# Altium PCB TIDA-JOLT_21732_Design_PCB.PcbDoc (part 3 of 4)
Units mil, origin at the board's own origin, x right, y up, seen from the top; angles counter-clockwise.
Board outline 5511.81 x 3149.61 mil, 4 copper layers (Top Layer, Power, Ground, Bottom Layer), stack 104.204 mil thick; 440 components, 201 nets, 1044 pads, 391 vias.
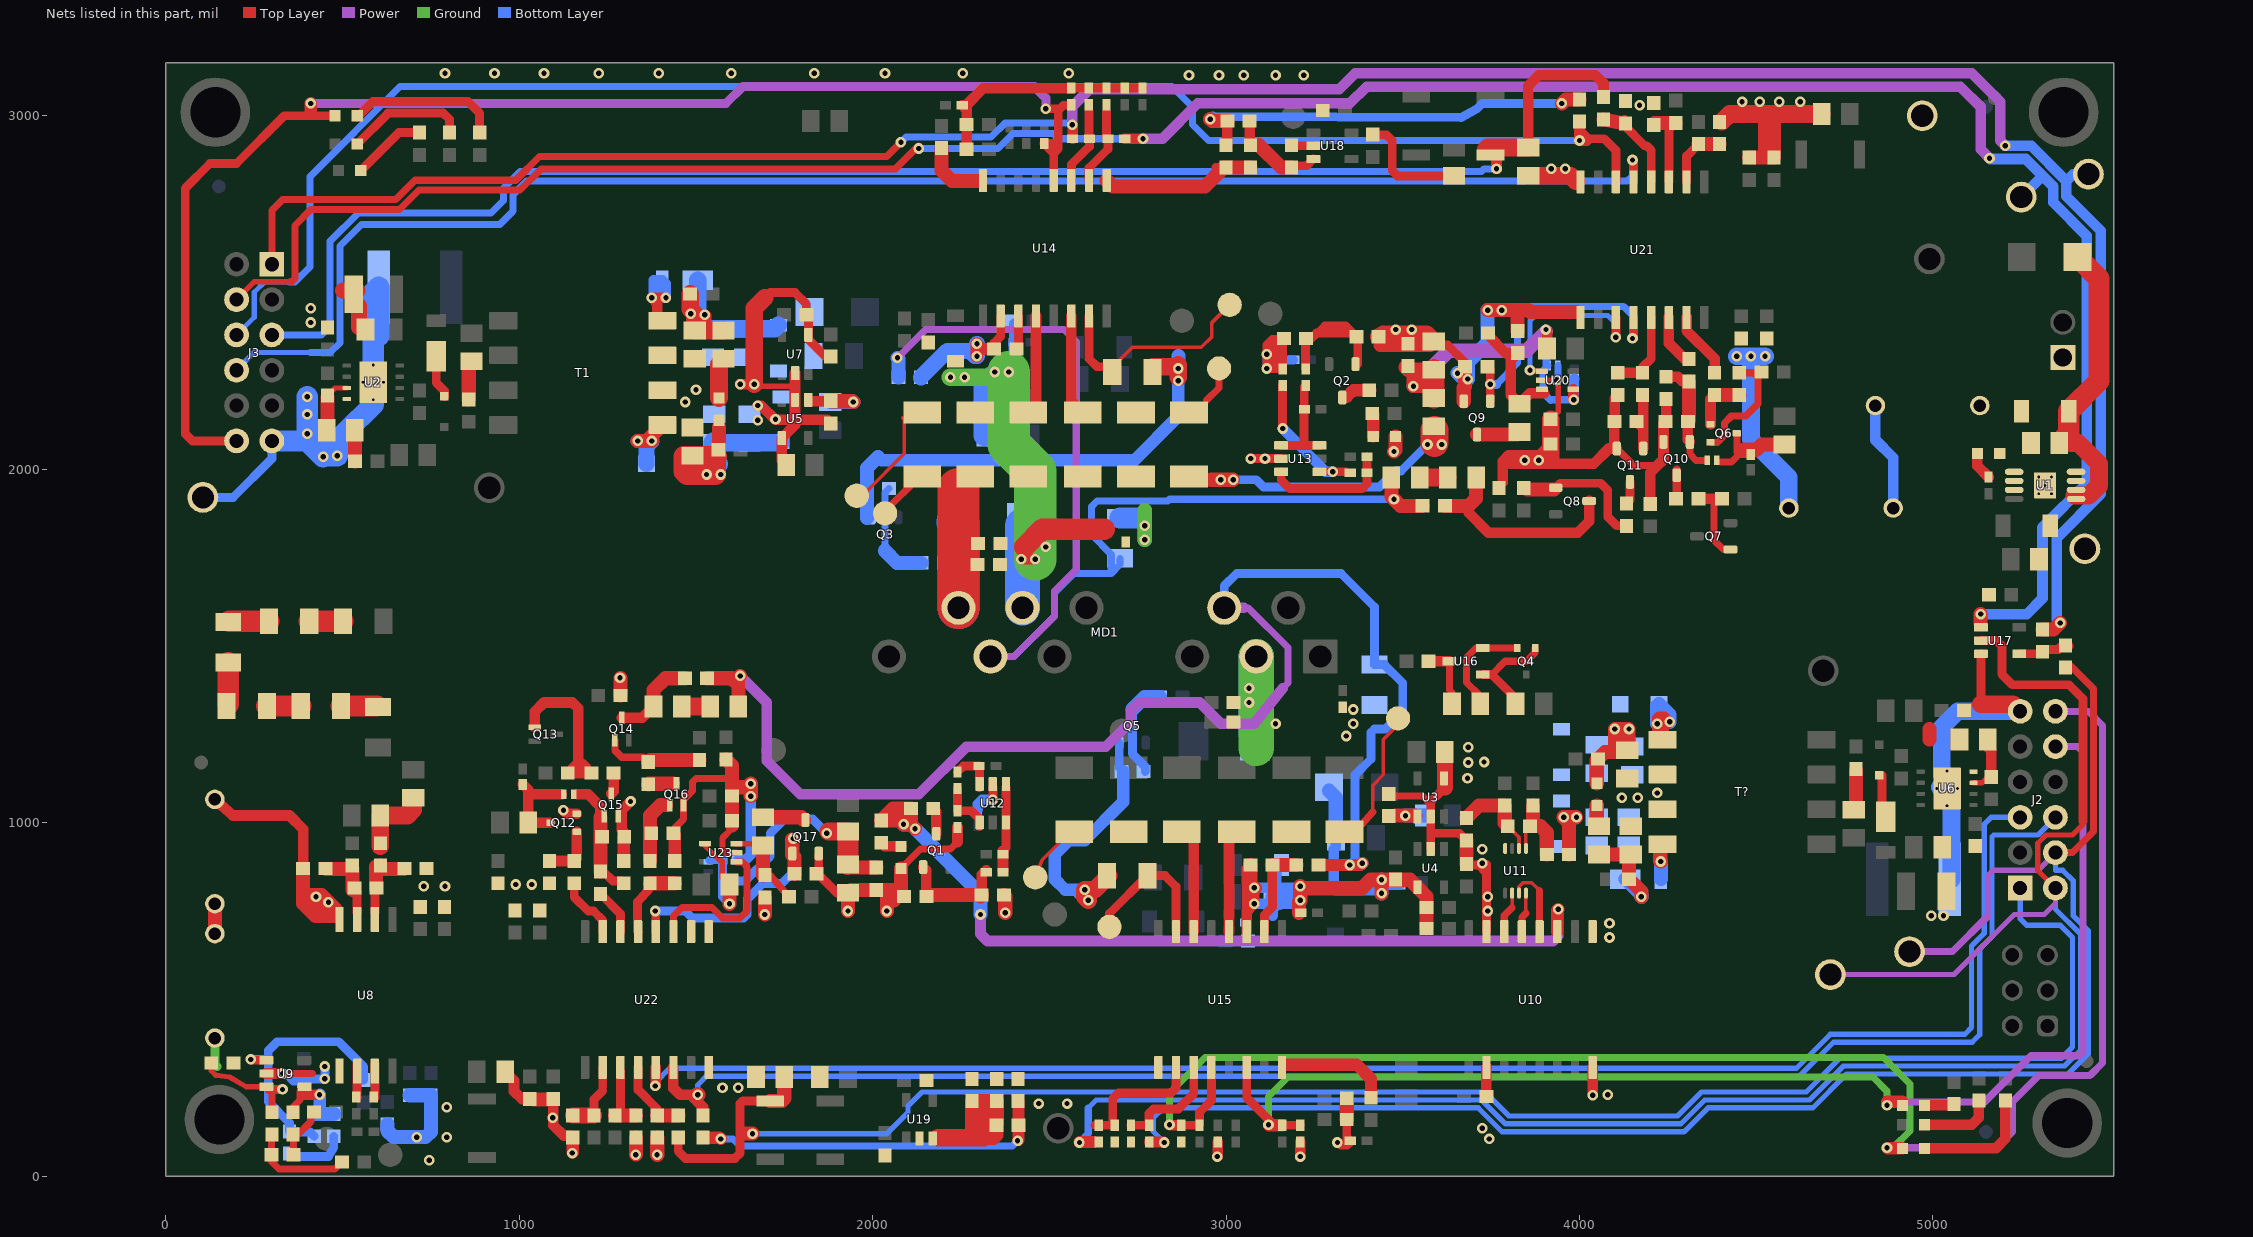
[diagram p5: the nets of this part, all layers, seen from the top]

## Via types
v1: diameter 30, hole 15, Top Layer to Bottom Layer, 378 vias
v2: diameter 19.68, hole 7.87, Top Layer to Bottom Layer, 13 vias

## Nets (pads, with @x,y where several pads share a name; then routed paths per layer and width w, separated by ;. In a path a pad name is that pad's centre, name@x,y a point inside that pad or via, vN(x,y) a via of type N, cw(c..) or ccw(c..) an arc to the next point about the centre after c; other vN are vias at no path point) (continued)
Gate_U: C80.1 D21.2 MD1.13 R63.2 R65.2 R66.2 R67.2 R68.2 R69.2 R70.2 R79.2 R122.2 TP11.1 | length 1515.2
  Top Layer w20: TP11.1@2035,1875 2035,1881.34 2133.11,1979.45 R70.2@2140,1979.45
  Top Layer w40: R63.2@2595,1979.45 R63.2@2598.5,1975.94 ; 2957.99,1970 v1(2985,1970) v1(3020,1970)
  Top Layer w80: 3590,2075 R122.2@3590,2110
  Top Layer w120: MD1.13@2242.76,1607.8 2242.76,1942.76
  Bottom Layer w25: v1(2985,1970) v1(3020,1970) 3085,1970 3105,1950 3435,1950 3480,1995 3495,1995 v1(3570,2070) v1(3610,2070)
  Bottom Layer w120: D21.2@2240.17,1850 2242.76,1847.42 MD1.13@2242.76,1607.8
GND: C1.2 C2.2 C3.2 C4.2 C5.2 C10.2 C11.2 C15.2 C17.2 C23.2 C24.2 C25.2 C36.2 C38.2 C43.2 C44.1 C46.1 C49.2 C55.1 C68.1 C71.2 C81.2 C82.2 C83.2 C84.2 C85.2 C86.2 C89.1 C90.2 C92.2 C93.2 C94.2 C95.2 C96.2 C97.2 C100.2 C101.1 C102.1 C103.2 C104.1 C105.2 C106.1 C108.1 C112.2 C118.1 C120.1 C121.1 C125.2 C132.1 C134.1 C135.1 C136.1 D7.1 J1.1 J2.11 J3.11 R9.1 R11.1 R20.1 R21.1 R40.1 R114.1 R115.1 R116.1 R117.1 R118.2 R120.2 R126.2 R143.2 R145.2 R151.2 TP2.1 TP23.1 TP24.1 U1.3 U1.4 U1.5 U1.6 U1.7 U1.9 U2.8 U2.9@587.1,2245.76 U6.8 U6.9@5040.13,1096.84 U8.5 U9.2 U10.2 U10.8 U14.9 U15.9 U17.3 U18.2 U19.2 U21.8 U22.8 | length 6379.4
  Top Layer w20: v1(330,290) 415,290
  Top Layer w25: C83.2@2561.65,3078.35 C85.2@2763.31,3078.35 ; 2971.5,2853.5 C103.2@3068.7,2853.5 ; R115.1@3185,2921.5 3191.5,2915 U18.2@3246.97,2915 ; C90.2@3341.5,160 3341.5,109.88 C97.2@3351.38,100 ; R114.1@3415,2946.5 3453.5,2946.5 3470,2930 3470,2845 3485,2830 R126.2@3645,2830 ; 5135,1335 5135.87,1335.87 U17.3@5135.87,1477.6
  Top Layer w30: U9.2@284.61,290 v1@326.44,290 ; R145.2@960,295 985,270 985,240 1007.99,217.01 C125.2@1041.3,217.01 ; 1096.3,143.7 1126.5,113.5 C136.1@1146.46,113.5 ; v1@1096.3,153.7 C121.1@1096.3,218.5 ; C86.2@2253.62,3030 2265.68,3017.94 ; C68.1@2265.68,2905.35 C71.2@2265.68,2975.35 2265.68,3017.94 ; C83.2@2561.65,3078.35 2313.35,3078.35 2265.68,3030.68 2265.68,3017.94 ; v1@2976.06,56.06 C95.2@2976.06,96.38 ; v1(3210,55) C96.2@3210,96.38 ; v1@3325.79,90 3341.38,90 C97.2@3346.38,95 ; C55.1@3736.5,225 3736.5,306.89 U10.2@3737.05,307.44 ; v1@4037.05,233.43 U10.8@4037.05,307.44
  Top Layer w35: v1@1151.46,66.46 C136.1@1151.46,108.5
  Top Layer w40: R11.1@535,2110 535.51,2035.17 R9.1@535.6,2022.61 ; C125.2@1041.3,217.01 C121.1@1091.3,217.01 ; v1@1330.58,60.58 C134.1@1330.58,108.5 ; v1@1390.29,60.29 C132.1@1390.29,108.5 ; U14.9@2662.18,2817.28 2679.46,2800 2940,2800 2993.5,2853.5 C104.1@3000,2853.5 C103.2@3068.7,2853.5 ; C90.2@3341.5,160 C89.1@3341.5,220 ; C108.1@4480,2881.5 4525,2881.5 ; 4525,2980 4525,2881.5 ; 4550,3005 C112.2@4550,2881.5 4525,2881.5 ; 4990,1235 4990,1265
  Top Layer w45: 500.76,2505.76 C2.2@542.13,2505.76 ; C3.2@547.1,2401.5 C2.2@547.1,2462.1
  Top Layer w50: R118.2@3855,2830 3975,2830 3990,2815 ; C135.1@4402.8,2982.8 4425,3005 4550,3005 R120.2@4685,3005 ; 5135,1335 5226.73,1335 J2.11@5246.77,1314.96
  Ground w25: C36.2@138.7,390.47 138.7,316.3 145,310
  Bottom Layer w25: TP23.1@105,1920 190,1920 300,2030 J3.11@300,2080 ; v1(330,290) 340,290 361.5,268.5 C44.1@390,268.5 396.5,275 v1(450,275) v1(450,310)
  Bottom Layer w30: v1(330,290) v1@330.47,289.53
  Bottom Layer w40: C49.2@626.69,146.54 626.69,128.31 645,110 v1(710,110) 735,110 750,125 C43.2@750,223.5 ; C46.1@690,228.5 C43.2@750,228.5
  Bottom Layer w50: v2@5020,1100 5052.36,1067.64 C23.2@5052.36,840 ; 5025,1135 5025,1270 5069.96,1314.96 ; 5077.76,1314.96 5069.96,1314.96 ; J2.11@5246.77,1314.96 5069.96,1314.96
  Bottom Layer w60: J3.11@300,2080 400,2080 ; v1(400,2205) v1(400,2155) v1(400,2100) 400,2080 ; 511.85,2108.15 510,2106.3 ; 602.64,2377.36 C1.2@602.64,2515 587.1,2499.46 v2(587.1,2294.97) v2(587.1,2196.55) 587.1,2183.39 510,2106.3 ; 400,2080 483.7,2080 510,2106.3 ; 400,2080 v1(445,2035) 448.03,2038.03 v1(485,2038.03) 485,2081.3 510,2106.3
  other v1: 745,45 2975,55 1330,60 1390,60 1150,65 3315,95 3745,105 795,110 3725,135 1095,165 795,195 2470,205 2550,205 4037.05,228.43 4080,230 1575,250 1620,250 4995,736.65 5030,736.65 410,2415 410,2455 3920,2850 3960,2850 4170,3030 4460,3040 4510,3040 4565,3040 4625,3040 2895,3115 2980,3115 3050,3115 3140,3115 3220,3115 790,3120 930,3120 1070,3120 1225,3120 1395,3120 1600,3120 1835,3120 2035,3120 2255,3120 2555,3120
  other v2: 5040.13,1047.63 5010.99,1096.84 5069.26,1096.84 5040.13,1146.06 5299.69,1930.51 5335.12,1930.51 5317.4,1954.13 5299.69,1977.76 5335.12,1977.76 557.96,2245.76 616.23,2245.76
INL+: J2.2 R88.2 TP14.1 U17.2 | length 5392.5
  Top Layer w15: J2.2@5346.77,814.96 5296.72,865.01 5296.72,941.72 5320.01,965.01 5395.01,965.01 5424.68,994.68 5424.68,1005
  Top Layer w25: U17.2@5135.87,1515 5180,1515 5195,1500 5195,1420 5225,1390 5385,1390 5424.68,1350.32 5424.68,1005
  Top Layer w35: v1@2586.38,96.38 R88.2@2628.19,96.38
  Power w15: TP14.1@4710,570 5060,570 5230,740 5315.04,740 5346.77,771.73 J2.2@5346.77,814.96
  Bottom Layer w15: 2610,192.8 2632.5,215.3 ; 2635,215.3 2632.5,215.3 ; J2.2@5346.77,814.96 5346.77,754.98 5417.45,684.3 5417.45,355.7 5372.8,311.06 4746.55,311.06 4650.79,215.3 4354.3,215.3 4286.55,147.55 3790.68,147.55 3722.93,215.3 2632.5,215.3
  Bottom Layer w20: v1(2585,95) 2610,120 2610,192.8
INL-: J2.4 R90.2 R109.2 TP16.1 | length 4744.8
  Top Layer w20: J2.4@5346.77,914.96 5394.96,914.96 5454.63,974.63 5454.63,1378.88 R109.2@5390,1443.5
  Top Layer w30: R90.2@2782.13,96.38 v1@2823.62,96.38
  Power w15: 5155,735 5155,850 5170,865 5296.81,865 J2.4@5346.77,914.96
  Power w20: TP16.1@4933.78,635 5055,635 5155,735
  Bottom Layer w15: v1(2825,95) 2793.94,126.06 2793.94,163.94 2822.85,192.85 3713.63,192.85 3781.38,125.1 4295.85,125.1 4363.6,192.85 4660.09,192.85 4755.85,288.61 5382.1,288.61 5439.9,346.4 5439.9,693.6 5396.72,736.78 5396.72,835.65 5367.46,864.91 5346.77,864.91 J2.4@5346.77,914.96
INU+: J3.4 R62.2 TP13.1 U17.1 | length 7295.8
  Top Layer w15: J3.4@200,2480 250,2530 355,2530
  Top Layer w20: 355,2530 365,2540 365,2690 410.1,2735.1 661.37,2735.1 716.37,2790.1 1002.55,2790.1 1062.45,2850 2065,2850 2130,2915 v1(2130,2907.5)
  Top Layer w30: R62.2@2713.09,2935 v1(2765,2935)
  Top Layer w40: 5135,1565 v1(5135,1590)
  Power w30: v1(2765,2935) 2820,2935 2920,3035 3350,3035 3397.55,3082.55 5077.45,3082.55 5135,3025 5135,2905 v1(5160,2880)
  Bottom Layer w20: v1(2130,2907.5) 2354.68,2907.5 2397.18,2950 2510,2950 2525,2935 v1(2765,2935)
  Bottom Layer w30: v1(5135,1590) 5265,1590 5310,1635 5310,1835 5435,1960 5435,2660 5340,2755 5340,2800 5262.45,2877.55 5162.45,2877.55 v1(5160,2880) ; TP13.1@5250,2770 5307.5,2827.5
INU-: J3.1 R64.2 R108.2 TP15.1 | length 7129.6
  Top Layer w20: J3.1@300,2580 300,2732.55 330,2762.55 650,2762.55 705,2817.55 990,2817.55 1057.45,2885 2040,2885 v1(2080,2925)
  Top Layer w30: R64.2@2565.85,2935 v1@2565.85,2974.15
  Top Layer w40: R108.2@5310,1546.5 5341.5,1546.5 v1(5360,1565)
  Power w30: v1(2565,2975) 2565,3026.38 2613.62,3075 3320,3075 3365,3120 5110,3120 5190,3040 5190,2930 v1(5205,2915)
  Bottom Layer w20: v1(2080,2925) 2095,2940 2335,2940 2375,2980 2560,2980 v1(2565,2975)
  Bottom Layer w30: v1(5205,2915) 5277.96,2915 5377.45,2815.51 ; v1(5360,1565) 5350,1575 5350,1805 5475,1930 5475,2675 5377.45,2772.55 5377.45,2815.51 ; TP15.1@5440,2835 5396.94,2835 5377.45,2815.51
ISO_GND_L: C18.1 C19.2 C20.2 C21.2 C22.2 C27.2 C28.2 C29.2 C32.1 C34.1 C35.1 C37.1 C42.2 C45.1 C51.2 C52.2 C53.1 C54.2 C56.1 C58.1 C59.1 C60.2 C61.2 C64.2 C66.2 C67.2 C74.1 C75.1 C91.2 C99.2 C122.1 C123.2 C124.1 C126.2 C127.1 C128.2 C130.2 C131.2 C133.2 C138.2 D10.2 D13.2 D18.1 D19.1 D26.1 D30.2 D42.2 MD1.6 Q12.2 Q15.2 Q16.2 Q17.2 R41.1 R56.1 R82.1 R84.1 R96.1 R158.1 R161.1 R162.1 R163.1 R166.1 R167.1 T?.6 T?.7 U3.2 U3.4 U4.2 U4.4 U8.4 U10.9 U10.15 U11.8 U12.2 U15.3 U22.9 U22.10 U23.2 | length 6443
  Top Layer w18: 1601.5,982.95 1575,956.46 1575,925 1585,915 U23.2@1614.29,915
  Top Layer w20: R166.1@1436.5,970 1436.5,981.5 1464.69,1009.69 Q16.2@1464.69,1048.5 1464.69,1064.69 1490,1090 1490,1115 1500,1125 1601.5,1125 ; D19.1@2080.24,869.76 2135.47,925 2220,925 2240,945 ; C19.2@3460,1081.5 3466.5,1075 3555,1075 3571.02,1058.98 3578.98,1058.98
  Top Layer w25: Q17.2@1847.4,909.02 1847.4,852.17 1898.31,801.26 R162.1@1930,801.26 ; v1(2340,1065) U12.2@2340,1099.13 ; U4.2@3578.98,925.39 3578.98,970 ; 3618.98,1098.98 3578.98,1058.98 U3.2@3578.98,1017.13 3578.98,970 ; C56.1@3680.28,882.76 3683.03,880 3714.09,880 3737.05,857.05 ; C58.1@3680.28,949.76 3660.04,970 3578.98,970 ; U10.15@3737.05,691.3 3737.05,857.05 ; v1@3737.05,881.93 3737.05,857.05
  Top Layer w30: C37.1@138.7,1065.75 190,1020 350,1020 388.5,981.5 C51.2@388.5,870 ; v1(1125,1035) 1134.41,1025.59 Q12.2@1163.07,1025.59 ; R163.1@1295.67,958.5 1295.67,974.33 1290,980 1290,1035 v1(1315,1060) ; 2240,945 R56.1@2240,986.38 ; U15.3@3058.31,691.3 3058.31,748.31 ; C99.2@3068.5,880 3058.31,869.8 3058.31,748.31 ; v1(3080,815.43) v1(3080,770) 3058.31,748.31
  Top Layer w35: C131.2@1295.67,891.5 R163.1@1295.67,958.5 ; C133.2@1440,891.5 R166.1@1440,966.5
  Top Layer w40: C51.2@388.5,870 388.5,795 ; R158.1@1286.5,1360 v1@1286.5,1408.5 ; C138.2@1585,1178.5 1601.5,1162.01 1601.5,1125 1601.5,1100 ; C126.2@1601.5,991.5 C126.2@1601.5,1005 C122.1@1601.5,1075 1601.5,1100 ; v1(1655,1075) v1(1655,1110) 1645,1100 1601.5,1100 ; v1(1695,740) R161.1@1695,788.5 ; v1(1930,750) R162.1@1930,801.26 1938.5,809.76 C130.2@2010,809.76 2040.12,809.76 ; v1@2040.12,750.12 2040.12,780 ; 2060.47,780 2040.12,780 ; D19.1@2080.24,869.76 2080.24,799.76 2070.24,809.76 2040.12,809.76 ; C60.2@2371.5,795 2375,791.5 v1(2375,745) ; C99.2@3068.5,880 3068.5,826.93 v1(3080,815.43) v1@3080.96,814.47 ; R41.1@3206.38,745 v1@3206.38,776.38 ; v1(3210,780) v1(3210,820) ; v1@3215,814.47 3384.47,814.47 3408.5,838.5 v1(3440,838.5) ; v1(3440,800) v1(3440,838.5) ; C53.1@3567.48,700 3567.48,791.22 U4.4@3541.57,817.13 3520.2,838.5 C21.2@3478.98,838.5 v1(3440,838.5) ; C56.1@3680.28,882.76 C58.1@3680.28,949.76 ; C59.1@3970.47,910 3970.47,999.53 v1(3955,1015) v1@3989.6,1015 ; 388.5,795 440,795 v1(460,775) 480,755 480,735.83 447.68,735.83 ; 388.5,795 447.68,735.83 ; 388.5,795 388.5,771.5 424.17,735.83 447.68,735.83 ; 2040.12,780 2040.12,809.76
  Top Layer w45: 3618.98,1098.98 C18.1@3618.98,1200
  Ground w100: 3085,1210 3085.28,1210.28 MD1.6@3085.28,1470
  Bottom Layer w30: 1620,895 1640.87,895 1655,909.13 v1(1655,1075) v1(1655,1110) ; C64.2@2297.32,1038.62 2297.32,1052.32 2310,1065 v1(2340,1065) ; v1(3080,770) C66.2@3132.09,770 ; v1(3080,815.43) 3137.09,815.43 v1@3205.43,815.43 ; 3132.09,737.09 C66.2@3132.09,770 ; C66.2@3132.09,790 C66.2@3132.09,770 ; v1(3210,820) v1(3210,780) 3200,770 3137.09,770 C66.2@3132.09,770 ; D30.2@3308.98,814.47 3305,818.44 3305,925 3310.47,930.47 C20.2@3310.47,957.27
  Bottom Layer w40: C66.2@3132.09,790 C66.2@3137.09,790 ; C66.2@3137.09,767.29 3137.09,770 C66.2@3137.09,790 ; C67.2@3146.93,880 3137.09,870.16 3137.09,815.43 C66.2@3137.09,790 ; 3180,790 C66.2@3137.09,790 ; D10.2@3291.26,1090 3310.47,1070.79 C20.2@3310.47,957.27 ; D30.2@3308.98,814.47 3425.53,814.47 ; v1(3440,800) v1(3440,838.5) 3448.5,830 C54.2@3488.5,830
  Bottom Layer w100: D26.1@3085.28,1250 MD1.6@3085.28,1470
  other v1: 4085,675 4085,715 2040,750 3740,750 425,790 3740,790 730,820 790,820 990,825 1035,825 3725,885 3725,925 3991.48,1015 4120,1070 4165,1070 4220,1084 3683.03,1125.39 3685,1170 3730,1171.5 3685,1212.91 3340,1245 3140,1280 3360,1280 3360,1320 3065,1340 3065,1380 1285,1410
ISO_GND_U: C7.2 C8.2 C9.2 C12.1 C13.1 C14.1 C16.1 C30.1 C31.2 C33.2 C39.2 C40.2 C62.2 C63.2 C65.2 C69.2 C70.2 C78.1 C79.1 C80.2 C87.2 C88.2 C107.1 C109.2 C110.2 C111.1 C113.1 C114.2 C115.2 C117.2 C119.2 C137.2 D4.2 D9.1 D17.2 D20.1 D21.1 D25.2 D36.2 MD1.11 Q6.2 Q9.2 Q10.2 Q11.2 R57.1 R69.1 R74.1 R78.1 R131.1 R132.1 R135.1 R138.1 R141.1 R142.1 T1.6 T1.7 U5.2 U5.4 U7.2 U7.4 U13.2 U14.3 U20.2 U21.9 | length 7597.1
  Top Layer w15: v1(1665,2240) 1670,2235 1780.28,2235 ; U20.2@3903.62,2251.3 3928.7,2251.3 3940,2240 3940,2162.8 C109.2@3918.5,2141.3
  Top Layer w20: Q11.2@4105.51,2058.54 4154.06,2010 4213.11,2010 4216.56,2006.56 ; Q6.2@4370.51,2075.71 4390.71,2075.71 4410,2095 4410,2130.59 4429.41,2150 4470,2150 4505,2185 4505,2260 4492.2,2272.8 C114.2@4452.24,2272.8
  Top Layer w25: 1695,2485 1710,2500 1780,2500 1812.19,2467.81 C40.2@1812.19,2437.14 ; C40.2@1818.1,2431.23 U7.4@1818.1,2380.01 1818.1,2367.9 1867.5,2318.5 C39.2@1881.3,2318.5 ; C88.2@2412.18,2345.68 U14.3@2412.18,2433.43 ; v1(3070,2030) v1(3110,2030) U13.2@3155.87,2030 ; 3134.72,2345.75 3160,2345.75 ; R57.1@3158.62,2285 3140,2285 ; R57.1@3160,2283.62 3160,2325 ; C62.2@3163.5,2370 C62.2@3160,2366.5 ; R132.1@3578.15,2351.54 3626.38,2351.54 3676.42,2301.5 R141.1@3676.42,2290.04 ; v1(3115,2325) v1(3115,2285) 3140,2285 ; v1(3115,2325) 3140,2325 ; v1(3115,2325) 3115,2351.02 3130.47,2366.5 C62.2@3160,2366.5 ; 3140,2285 3140,2325 ; 3140,2325 3160,2325 ; 3160,2325 3160,2345.75 ; 3160,2345.75 C62.2@3160,2366.5
  Top Layer w30: v1(1625,2240) v1(1665,2240) ; v1(1675,2180) 1685,2180 1725,2140 1780.28,2140 ; C30.1@1755.28,2012.14 1742.87,2024.54 U5.4@1742.87,2088.01 1780.28,2125.41 1780.28,2140 ; U7.2@1780.28,2271.32 1780.28,2235 U5.2@1780.28,2196.27 1780.28,2142.14 ; C31.2@1881.3,2129.38 1870.68,2140 1782.41,2140 ; v1(2420,1745) v1(2460,1745) ; C137.2@3782.52,1962.8 3782.52,2022.52 3800,2040 3887.2,2040 ; 3805,2015 3915,2015 ; C107.1@3918.5,2071.3 3887.2,2040 ; R142.1@4098.5,2135 4098.5,2065.55 Q11.2@4105.51,2058.54 4083.54,2058.54 4040,2015 3915,2015 ; R142.1@4100,2135.79 C119.2@4100,2200 ; R135.1@4200,1901.5 4200,1990 4216.56,2006.56 4237.6,2027.6 Q10.2@4237.6,2077.24 4237.6,2129.09 R138.1@4243.5,2135 4245,2136.5 C117.2@4245,2198.5 ; 1780.28,2140 1780.28,2142.14 ; 1780.28,2140 1782.41,2140 ; 1780.28,2142.14 1782.41,2140 ; 3887.2,2040 3890,2040 3915,2015
  Top Layer w40: 3436.54,2351.54 3578.15,2351.54 R132.1@3587.91,2361.3 ; v1(3474.87,2050) 3479.46,2054.59 D20.1@3479.46,2092.76 ; Q9.2@3672.6,2192.24 3672.6,2230.63 ; 3676.42,2234.45 R141.1@3676.42,2290.04 ; v1(3740,2450) v1(3780,2450) 3825,2450 ; R131.1@3825,2391.5 3825,2450 ; 3990,2445 3860,2445 3855,2450 3825,2450
  Top Layer w50: v1(1665,2240) 1665,2455 1695,2485 ; C63.2@3431.5,2375 3435,2371.5 3444.57,2381.06 3568.15,2381.06 R132.1@3587.91,2361.3 ; 3918.5,2025 C109.2@3918.5,2141.3
  Top Layer w60: 2430,1780 2480,1830 2655,1830
  Ground w40: v1(2770,1800) v1(2770,1840) 2770,1885
  Ground w50: v1(2220,2260) v1(2260,2260) 2370,2260 v1(2385,2275)
  Ground w120: v1(2385,2275) 2385,2070 2460,1995 v1(2460,1745)
  Bottom Layer w20: v1@3938.78,2255.08 D36.2@3938.78,2293.62
  Bottom Layer w25: 3161.57,2305 3115,2305 ; C65.2@3191.38,2309.21 3169.21,2309.21 ; 3115,2305 v1(3115,2285) 3145,2285 3169.21,2309.21 ; 3115,2305 v1(3115,2325) 3150,2325 3165.79,2309.21 3169.21,2309.21
  Bottom Layer w30: v1(2220,2260) v1(2260,2260) 2335,2260 ; v1(2345,2275) v1(2385,2275) 2400,2290 C78.1@2400,2358.23 ; C78.1@2400.47,2358.7 C79.1@2400.47,2410.83
  Bottom Layer w40: 2747.91,1862.09 v1(2770,1840) v1(2770,1800) ; v1(3780,2450) v1(3740,2450) 3740,2358.58 3683.61,2302.19 v1@3683.61,2265.14 ; v1@3683.61,2265.14 v1(3683.61,2255) 3671.75,2255 v1(3655,2271.75) 3677,2271.75 v1@3683.61,2265.14
  Bottom Layer w50: 2423.86,1780 v1(2490,1780) ; v1(4445,2320) v1(4485,2320) ; v1(4525,2320) v1(4485,2320) ; C16.1@4592.36,1890 4592.36,1977.64 4485,2085 v1(4485,2320)
  Bottom Layer w60: C70.2@2315.98,2095 2315.98,2249.02 ; 2320,2230 2335,2260 ; R74.1@2700,1862.09 2747.91,1862.09
  Bottom Layer w100: MD1.11@2423.86,1607.8 2423.86,1780 D21.1@2423.86,1840.33
  other v1: 3845,2025 3885,2025 1675,2138.5 1725,2141.3 1469.87,2190 1500,2225 3935,2251.3 3480,2395 3525,2395
NetC6_1: C6.1 R1.1 | length 111
  Top Layer w40: C6.1@857.1,2197.26 857.1,2297.1 R1.1@865,2305
NetC7_1: C7.1 C8.1 C9.1 D3.1 D4.1 R2.1 R3.2 | length 637.5
  Top Layer w25: v1(1485,2440) 1496.5,2440 1526.61,2440 1531.5,2435.11 1531.5,2392.39
  Top Layer w50: R2.1@1483.5,2495.5 1483.5,2453 1496.5,2440 1496.85,2439.66 C9.1@1496.85,2392.39 1531.5,2392.39 ; 1535,2392.39 1577.92,2392.39 R3.2@1578.14,2392.61
  Bottom Layer w50: D3.1@1505.2,2535 1505.2,2414.8 1522.98,2397.02 C7.1@1548.2,2397.02 C8.1@1639.22,2397.02 1723.14,2397.02 D4.1@1733.2,2407.08
  other v1: 1525,2437.14
NetC10_1: C10.1 C11.1 D1.1 U1.1 U1.2 | length 1389.8
  Top Layer w18: U1.1@5405,1915.75 5455.35,1915.75 5484.47,1944.86 5484.47,2015.14 5409.61,2090 5373.27,2090 C11.1@5357.4,2074.13 5390.87,2074.13 5460,2005 5460,1955 5446.34,1941.34 U1.2@5405,1941.34
  Top Layer w50: 5390.87,2074.13 5410.87,2074.13 5470,2015 5470,1955 5440,1925 5400,1925
  Top Layer w60: C11.1@5373.27,2090 5384.33,2101.06 C10.1@5384.33,2164.13 5470,2249.8 5470,2538.74 D1.1@5408.74,2600
NetC12_2: C12.2 C13.2 C14.2 D6.1 D8.2 D9.2 R8.1 | length 683.5
  Top Layer w40: v1@1565,1990 1565,2118.5
  Top Layer w60: v1@1555,1985 v1(1530,1985) 1475,1985 1466.4,1993.6 1466.4,2035 1558.5,2035
  Bottom Layer w50: C12.2@1551.46,2075 C13.2@1651.46,2075 D9.2@1739.47,2075
  Bottom Layer w60: D8.2@1470.12,2015 1560,2015 ; 1551.46,2023.54 C12.2@1551.46,2075
  other v1: 1570,1985
NetC15_1: C15.1 C16.2 | length 310.8
  Bottom Layer w30: C15.1@4837.36,2180 4837.36,2082.64 4887.64,2032.36 C16.2@4887.64,1890
NetC19_1: C19.1 R10.1 U3.1 | length 109.6
  Top Layer w40: 3478.98,1019.76 v1(3507.47,1019.76) U3.1@3535.96,1019.76
  Bottom Layer w40: v1(3507.47,1019.76) 3507.71,1020 R10.1@3560,1020
NetC26_1: C26.1 R12.1 | length 111.3
  Top Layer w40: R12.1@4776.1,1036.85 4782.41,1043.16 C26.1@4782.41,1145.55
NetC27_1: C27.1 C28.1 C29.1 D12.1 D13.1 R13.1 R14.2 | length 293.6
  Top Layer w40: R14.2@4048.98,910 4138.98,910 4140.47,908.5 R13.1@4140.47,840 4175,805.47 v1(4175,790)
  Bottom Layer w40: D12.1@4129.8,840 4175,794.8 v1(4175,790)
NetC31_1: C31.1 R15.1 U5.1 | length 179.7
  Top Layer w30: 1831.27,2192.38 C31.1@1881.3,2192.38
  Top Layer w40: C31.1@1881.3,2192.38 1942.62,2192.38 v1(1945,2190)
  Bottom Layer w40: R15.1@1880,2190 v1(1945,2190)
NetC32_2: C32.2 C34.2 C35.2 D15.1 D16.2 D18.2 R19.1 | length 333.9
  Top Layer w40: D15.1@4048.98,1111.5 4048.98,1177.05 R19.1@4051.93,1180 4071.93,1200 4098.98,1200 ; 4098.98,1200 4100,1201.02 v1(4100,1265) 4137.95,1265 4138.98,1263.98 4138.98,1200 4098.98,1200
  other v1: 4140,1265
NetC36_1: C36.1 C37.2 | length 84.7
  Top Layer w40: C36.1@138.7,685.75 C37.2@138.7,770.47
NetC41_1: C41.1 R29.1 R33.2 U9.4 | length 225.1
  Top Layer w20: R33.2@360,180.47 360,195 380,215 380,239.72 U9.4@392.87,252.6
  Top Layer w30: 390,230 415.47,230 v1(435,230)
  Bottom Layer w35: C41.1@435,190.63 v1(435,230)
  Bottom Layer w40: C41.1@420,175.63 R29.1@475,175.63
NetC41_2: C41.2 R30.2 R36.2 U9.1 | length 772.2
  Top Layer w25: v1(240,330) 242.6,327.4 U9.1@284.61,327.4
  Bottom Layer w25: v1(240,330) 290,330 ; C41.2@420,112.64 407.64,125 351.5,125 R30.2@350,126.5 350,150 290,210 290,280 290,355 315,380 489.25,380 560,309.25 R36.2@560,271.5
NetC47_1: C47.1 R32.2 R33.1 | length 151.4
  Top Layer w20: C47.1@361.5,60 361.5,115.98 372.28,115.98 410,153.7 410,172.28 R32.2@419.02,181.3
NetC47_2: C47.2 R37.2 R38.1 | length 293.8
  Top Layer w20: R38.1@300,117.48 298.5,115.98 C47.2@298.5,60 298.5,41.5 320,20 478.5,20 R37.2@498.5,40
NetC48_1: C48.1 C51.1 R34.1 U8.3 | length 205.6
  Top Layer w25: C48.1@533.5,815 541.38,807.13 U8.3@541.38,745.83
  Top Layer w40: C51.1@452.99,868.5 527.68,868.5 C48.1@527.68,810
NetC48_2: C48.2 C52.1 R35.1 U8.2 | length 200.3
  Top Layer w25: U8.2@591.38,745.83 C48.2@591.38,809.88
  Top Layer w40: C48.2@595,815 R35.1@595,875.55 ; R35.1@607.68,878.5 607.68,868.5 C52.1@673.39,868.5
NetC57_1: C57.1 C59.2 R44.2 U11.5 | length 235.4
  Top Layer w10: U11.5@3848.5,926.61 3848.5,978.5 C57.1@3860,990
  Top Layer w40: C57.1@3860,990 3890,990 3907.48,972.52 C59.2@3907.48,910 ; C57.1@3868.5,998.5 R44.2@3868.5,1048.5
NetC57_2: C57.2 C58.2 R43.2 U11.6 | length 249.6
  Top Layer w10: C57.2@3797.01,990 3828.82,958.19 U11.6@3828.82,926.61
  Top Layer w40: C58.2@3680.28,1012.76 3716.02,1048.5 R43.2@3788.5,1048.5 C57.2@3788.5,998.5
NetC60_1: C60.1 C61.1 Q1.1 R48.2 | length 319.8
  Top Layer w30: Q1.1@2142.83,874.02 2151.73,865.12 C61.1@2151.73,791.26 ; C60.1@2308.5,795 2308.5,852.13 R48.2@2321.38,865
  Top Layer w40: C61.1@2155.47,795 C60.1@2308.5,795 C60.1@2305,791.5
NetC62_1: C62.1 C63.1 Q2.1 R50.2 | length 433.8
  Top Layer w25: R50.2@3225,2283.62 3225,2368.5 C62.1@3226.5,2370 3241.02,2370 3256.02,2385 3260,2385 ; Q2.1@3372.4,2297.24 3372.4,2371.1 C63.1@3368.5,2375 C63.1@3358.5,2385 ; 3260,2385 C63.1@3358.5,2385 ; 3260,2385 3280,2405 3320,2405 3338.5,2405 C63.1@3358.5,2385
NetC81_1: C81.1 R62.1 U14.10 | length 211.9
  Top Layer w25: U14.10@2612.18,2817.28 2612.18,2852.18 2665.85,2905.85 R62.1@2665.85,2935 ; R62.1@2661.65,2939.2 2661.65,3011.1
NetC82_1: C82.1 R64.1 U14.11 | length 213.5
  Top Layer w25: U14.11@2562.18,2817.28 2562.18,2862.18 2613.09,2913.09 R64.1@2613.09,2935 ; R64.1@2611.65,2936.44 2611.65,3011.1
NetC88_1: C88.1 R73.1 U14.2 | length 425.6
  Top Layer w25: C88.1@2346.32,2342.82 C88.1@2343.5,2340 2343.5,2357.05 2362.18,2375.72 U14.2@2362.18,2433.43
  Top Layer w35: v1(2295,2320) v1(2295,2355) 2310,2340 C88.1@2343.5,2340
  Bottom Layer w45: R73.1@2136.5,2260 2211.5,2335 2275,2335 2290,2320 v1(2295,2320) v1(2295,2355)
NetC92_1: C92.1 R88.1 U15.10 | length 377.1
  Top Layer w25: R88.1@2628.19,143.62 2679.5,143.62 2679.5,219.5 2695,235 2845,235 2858.31,248.31 U15.10@2858.31,307.44
NetC93_1: C93.1 R90.1 U15.11 | length 308.4
  Top Layer w25: C93.1@2730.81,143.62 R90.1@2782.13,143.62 2782.13,177.13 2795,190 2865,190 2908.31,233.31 U15.11@2908.31,307.44
NetC99_1: C99.1 R100.1 U15.2 | length 265.3
  Top Layer w25: U15.2@3108.31,691.3 3108.31,738.31 3131.5,761.5 C99.1@3131.5,880
  Top Layer w40: C99.1@3131.5,880 R100.1@3198.5,880
NetC103_1: C103.1 R110.1 R115.2 U18.3 | length 297.1
  Top Layer w25: C103.1@3068.7,2916.5 3093.5,2916.5 ; R115.2@3166.5,2858.5 3227.87,2858.5 U18.3@3246.97,2877.6
  Top Layer w30: C103.1@3066.5,2918.7 R110.1@3066.5,2985
  Top Layer w40: 3093.5,2916.5 3156.5,2853.5 R115.2@3185,2853.5
NetC104_2: C104.2 R110.2 R111.1 | length 1189.6
  Top Layer w30: C104.2@3000,2916.5 3003.5,2920 R110.2@3003.5,2985
  Top Layer w40: v1(2955,2990) 2960,2985 R110.2@3003.5,2985 ; v1(3950,3035) 3961.5,3046.5 R111.1@4000,3046.5
  Bottom Layer w25: v1@2962.55,2997.55 3665,2995 3710,3020 3725,3035 v1(3950,3035)
  Bottom Layer w30: v1@2957.45,2987.55 v1(2955,2990) v1@2962.55,2997.55
NetC105_1: C105.1 R112.1 R117.2 U19.3 | length 515.5
  Top Layer w25: 2327.4,121.1 R112.1@2349.8,143.5
  Top Layer w40: 2281.3,136.3 R117.2@2281.3,212.01 2316.3,212.01 ; 2314.8,108.5 2342.32,108.5 2349.8,115.98 R112.1@2349.8,143.5 ; 2316.3,136.3 2316.3,212.01 ; R112.1@2351.3,145 C105.1@2351.3,212.01 2316.3,212.01
  Top Layer w50: 2185,108.5 2314.8,108.5
NetC106_2: C106.2 R112.2 R113.1 | length 1015.8
  Top Layer w35: R113.1@1520,108.5 1566.5,108.5 v1(1570,105) ; C106.2@2411.3,212.01 2412.8,210.51 R112.2@2412.8,143.5 v1@2412.8,102.8
  Bottom Layer w20: v1(1570,105) 1605,105 1625,85 2395,85 v1(2410,100)
NetC114_1: C114.1 Q6.1 R124.2 | length 157.8
  Top Layer w30: Q6.1@4370.51,2126.89 4370.51,2198.07 R124.2@4382.24,2209.8
  Top Layer w40: R124.2@4382.24,2209.8 C114.1@4452.24,2209.8
NetC115_1: C115.1 D35.2 D36.1 R122.1 R123.1 R132.2 U20.4 | length 1144.7
  Top Layer w30: R123.1@3907.91,2341.3 v1@3907.91,2392.09 ; U20.4@3982.2,2225.71 3982.2,2197.8 v1(3983.6,2196.4)
  Top Layer w40: C115.1@3507.91,2288.54 3515.16,2281.3 R132.2@3587.91,2281.3 ; 3530,2259.02 v1(3530,2235) ; 3555,2260 v1(3530,2235) ; 3587.91,2235 v1(3530,2235)
  Top Layer w60: R122.1@3587.91,2201.3 3587.91,2235 R132.2@3587.91,2281.3
  Power w40: v1(3530,2235) 3630,2335 3850,2335 v1@3905,2390
  Bottom Layer w20: D36.1@3905,2290 v1(3905,2395) ; D36.1@3911.22,2293.62 3896.53,2278.93 3896.53,2216.62 3918.15,2195 3919.55,2196.4 v1(3983.6,2196.4)
  Bottom Layer w30: v1(3983.6,2196.4) 3983.6,2254.31 D35.2@3985,2255.71
NetC116_1: C116.1 Q8.3 R137.2 | length 591.5
  Top Layer w30: 3686.3,1876.3 3742.6,1820 3995,1820 4027.24,1852.24 Q8.3@4027.24,1910
  Top Layer w40: R137.2@3619.02,1896.3 3686.3,1896.3 3707.52,1917.52 C116.1@3707.52,1976.3
NetC116_2: C116.2 R140.2 | length 80
  Top Layer w50: R140.2@3547.52,1976.3 C116.2@3627.52,1976.3
NetC117_1: C117.1 D31.2 Q10.1 R134.2 R138.2 | length 330.1
  Top Layer w20: Q10.1@4312.4,2077.24 4312.4,2042.6 4330,2025 D31.2@4355,2025
  Top Layer w30: C117.1@4245,2261.5 4278.5,2261.5 4291.5,2248.5 R134.2@4310,2248.5 ; R138.2@4306.5,2135 4306.5,2083.15 Q10.1@4312.4,2077.24
  Top Layer w40: R138.2@4306.5,2135 4310,2138.5 R134.2@4310,2248.5
NetC118_2: C118.2 R136.2 U21.4 | length 264.3
  Top Layer w25: C118.2@4127.62,2989.8 4127.62,2971.35 4183.98,2915 4190,2915 4202.91,2902.09 U21.4@4202.91,2813.23
  Top Layer w40: R136.2@4067.91,2989.8 C118.2@4120,2980
NetC119_1: C119.1 R139.1 U21.13 | length 236.9
  Top Layer w25: R139.1@4177.91,2272.8 4177.91,2287.91 4202.91,2312.91 U21.13@4202.91,2429.37
  Top Layer w30: C119.1@4107.91,2272.8 R139.1@4177.91,2272.8
NetC120_2: C120.2 R133.2 U21.3 | length 234.2
  Top Layer w25: U21.3@4252.91,2813.23 4252.91,2960.68 R133.2@4272.04,2979.8
  Top Layer w40: C120.2@4212.33,2979.8 R133.2@4272.04,2979.8
NetC128_1: C128.1 Q12.1 R146.2 | length 156
  Top Layer w30: C128.1@1085.67,891.5 R146.2@1155.67,891.5 1163.07,898.9 Q12.1@1163.07,974.41
NetC129_1: C129.1 Q14.3 R160.2 | length 252.1
  Top Layer w30: Q14.3@1290,1296.5 1347.95,1296.5 C129.1@1380,1328.54
  Top Layer w40: C129.1@1380,1328.54 1380,1375 1413.54,1408.54 R160.2@1468.5,1408.54
NetC129_2: C129.2 R165.2 | length 80
  Top Layer w50: C129.2@1460,1328.54 R165.2@1540,1328.54
NetC130_1: C130.1 D41.2 D42.1 R148.1 R150.1 R162.2 U23.4 | length 1012
  Top Layer w15: U23.4@1525.71,940.59 1525.71,934.6 1569.69,890.63 1574.37,890.63 1574.37,845.63 R150.1@1595,825
  Top Layer w40: v1(1595,770) R150.1@1595,825 ; R162.2@1930,881.26 1938.5,872.76 C130.1@2010,872.76
  Top Layer w50: v1@1875,975 R148.1@1930,975
  Top Layer w60: R162.2@1930,881.26 R148.1@1930,961.26
  Bottom Layer w25: D41.2@1539.63,893.41 1541.22,895 1575,895 1575,835 ; v1(1595,770) 1575,790 1575,835 ; v1(1870,970) 1830,1010 1750,1010 1710,970 1710,905 1640,835 1575,835
NetC131_1: C131.1 D33.2 Q15.1 R157.2 R163.2 | length 342.3
  Top Layer w25: R157.2@1230,861.5 1238.5,861.5 1265,835 1289.17,835 C131.1@1295.67,828.5
  Top Layer w30: 1165,1080 1195,1080 1230,1045 1230,1015
  Top Layer w40: R157.2@1230,861.5 1230,1015
NetC132_2: C132.2 R159.2 U22.4 | length 218
  Top Layer w25: U22.4@1336.26,307.44 1336.26,243.74 1390.29,189.71 C132.2@1390.29,171.5
  Top Layer w40: C132.2@1390.29,171.5 R159.2@1450,171.5
NetC133_1: C133.1 R164.1 U22.13 | length 207.4
  Top Layer w25: U22.13@1336.26,691.3 1335,692.56 1335,775 R164.1@1370,815
  Top Layer w40: R164.1@1370,828.5 C133.1@1440,828.5
NetC134_2: C134.2 R156.2 U22.3 | length 176.8
  Top Layer w25: R156.2@1266.26,176.11 R156.2@1270.87,171.5 ; R156.2@1286.26,186.88 U22.3@1286.26,297.44
  Top Layer w40: R156.2@1270.87,171.5 C134.2@1330.58,171.5
NetC135_2: C135.2 R168.2 U21.2 | length 180.3
  Top Layer w25: U21.2@4302.91,2813.23 4302.91,2885.97 R168.2@4336.75,2919.8
  Top Layer w40: R168.2@4336.75,2919.8 C135.2@4396.46,2919.8
NetC136_2: C136.2 R169.2 U22.2 | length 196
  Top Layer w25: R169.2@1211.17,171.5 1211.17,216.17 1236.26,241.26 ; 1236.26,251.26 U22.2@1236.26,307.44
  Top Layer w45: C136.2@1151.46,171.5 R169.2@1211.17,171.5
NetD2_1: D2.1 D5.1 | length 123.5
  Top Layer w25: D2.1@765,2319.8 765,2245 788.2,2221.8 D5.1@788.2,2205.92
NetD3_2: D3.2 T1.8 | length 321.9
  Top Layer w30: T1.8@1390.99,2439.66 1390.99,2469.01 v1(1375,2485) v1(1415,2485)
  Bottom Layer w30: v1@1380,2490 1390,2500 1390,2505 1385.75,2509.25 1385.75,2515.94 D3.2@1404.8,2535 ; v1@1380,2490 v1(1375,2485) v1(1415,2485) 1415,2524.8 D3.2@1404.8,2535 ; v1@1380,2490 1380,2535 D3.2@1404.8,2535
NetD6_2: D6.2 R3.1 | length 94.7
  Top Layer w50: D6.2@1565,2201.5 R3.1@1565,2296.22
NetD7_2: D7.2 R4.1 | length 79.4
  Top Layer w30: D7.2@5125.91,2044.13 5125.91,2009.25 R4.1@5157.4,1977.76
NetD8_1: D8.1 T1.5 | length 215.1
  Top Layer w40: v1(1335,2080) 1359.84,2080 ; v1(1375,2080) 1359.84,2080 ; T1.5@1405,2125.16 1359.84,2080
  Bottom Layer w40: v1(1335,2080) v1(1375,2080)
  Bottom Layer w45: D8.1@1359.88,2015 1359.88,2064.88 v1(1375,2080)
NetD11_1: D11.1 D14.1 | length 124.8
  Top Layer w25: D14.1@4856.1,1133.54 4856.1,1037.05 D11.1@4876.1,1017.05
NetD12_2: D12.2 T?.8 | length 88.8
  Top Layer w40: T?.8@4228.31,928.31 4228.31,891.69 v1(4230,890)
  Bottom Layer w40: D12.2@4230.2,840 v1@4230.2,889.8
NetD15_2: D15.2 R14.1 | length 58.5
  Top Layer w40: R14.1@4048.98,990 D15.2@4048.98,1048.5
NetD16_1: D16.1 T?.5 | length 307.8
  Top Layer w30: T?.5@4220,1250 v1(4220,1280) 4220,1295.06 4224.94,1300 4240,1300 v1(4255,1285) 4238.31,1268.31 ; T?.5@4238.31,1232.4 4238.31,1268.31 ; 4238.31,1271.69 4238.31,1268.31
  Bottom Layer w40: v1(4220,1280) 4220,1329.88 D16.1@4225.12,1335 4255,1305.12 v1(4255,1285) 4225,1285 v1(4220,1280)
NetD19_2: D19.2 R55.1 | length 60.3
  Top Layer w30: R55.1@2024.19,942.95 2034.38,932.76 D19.2@2080.24,932.76
NetD20_2: D20.2 R170.1 | length 63
  Top Layer w35: D20.2@3416.47,2092.76 R170.1@3416.47,2155.72
NetD22_2: D22.2 R75.2 | length 210.9
  Top Layer w25: D22.2@551.5,2845 658.82,2952.32 R75.2@717.95,2952.32
NetD23_2: D23.2 R76.2 | length 342.4
  Top Layer w25: D23.2@541.5,2920 629.05,3007.55 785,3007.55 802.95,2989.6 R76.2@802.95,2952.32
NetD24_2: D24.2 R77.2 | length 433.1
  Top Layer w25: D24.2@541.5,2995.83 585.67,3040 855,3040 887.95,3007.05 R77.2@887.95,2952.32
NetD27_2: D27.2 R102.2 | length 75
  Top Layer w30: D27.2@4976.5,200 R102.2@5051.5,200
NetD28_2: D28.2 R103.2 | length 210.3
  Top Layer w30: D28.2@4976.5,145 5110,145 5130,165 R103.2@5130,213.5
NetD29_2: D29.2 R104.2 | length 348
  Top Layer w30: D29.2@4976.5,78.35 5178.35,78.35 5205,105 R104.2@5205,213.5
NetD31_1: D31.1 D32.1 Q6.3 R119.1 | length 278.7
  Top Layer w20: 4398.78,2020 4430,2020 4451.65,2041.65 ; Q6.3@4445.31,2101.3 4445.31,2047.99 4451.65,2041.65 ; D32.1@4485,2041.65 4451.65,2041.65
  Top Layer w40: 4465,2055 4500,2055 4515,2070 R119.1@4580,2070
NetD33_1: D33.1 D38.1 Q12.3 R144.1 | length 259.1
  Top Layer w30: D38.1@1010,1108.35 1025.67,1092.68 R144.1@1025.67,1000 Q12.3@1088.27,1000 ; 1038.35,1080 D33.1@1120,1080
NetQ1_3: Q1.3 R52.1 | length 75.1
  Top Layer w30: R52.1@2171.5,1040 2180.24,1031.26 Q1.3@2180.24,968.5
NetQ2_3: Q2.3 R53.1 | length 74.7
  Top Layer w35: 3341.5,2205 3360.09,2223.59 R53.1@3408.5,2223.59
NetQ3_1: Q3.1 R80.1 R81.1 | length 1372.5
  Top Layer w50: R80.1@2792.09,2290 2860,2290 v1(2865,2285) ; v1@2865,2260 v1@2865,2295
  Bottom Layer w35: 2015,2035 2025,2025 2740,2025 2865,2150 v1(2865,2285)
  Bottom Layer w40: 1983.5,1861.5 R81.1@1983.5,1945 1983.5,2003.5 2015,2035 ; v1(2865,2285) 2865,2320
  other v1: 2865,2250
NetQ3_3: Q3.3 R79.1 R81.2 | length 298.2
  Bottom Layer w20: Q3.3@2035,1769.33 2035,1933.5 R81.2@2046.5,1945
  Bottom Layer w40: Q3.3@2035,1769.33 2069.33,1735 R79.1@2138.5,1735
NetQ4_1: Q4.1 R92.1 U16.1 | length 297.1
  Top Layer w20: 3752.17,1419.17 3789.57,1456.58 3850,1456.58 3874.57,1481.14 Q4.1@3874.57,1493.98
  Top Layer w25: U16.1@3726.22,1419.17 3752.17,1419.17 3818.98,1352.36 R92.1@3818.98,1336.58
NetQ4_2: Q4.2 R97.2 U16.2 | length 300.9
  Top Layer w20: R97.2@3718.98,1336.58 3718.98,1357.6 3680,1396.58 3680,1466.58 3707.4,1493.98 U16.2@3726.22,1493.98 Q4.2@3823.39,1493.98
NetQ5_1: Q5.1 R106.1 R107.1 | length 780.7
  Top Layer w50: v1(2610,780) 2600,790 v1(2600,810) 2627.91,810 R106.1@2667.91,850
  Bottom Layer w25: Q5.1@2697.6,1226.18 2697.6,1155.91 R107.1@2708.5,1145
  Bottom Layer w35: 2585,800 2605,780 v1(2610,780) 2600,790 v1(2600,810) 2545,810 2515,840 2515,910 2555,950 2600,950 2708.5,1058.5 R107.1@2708.5,1145
NetQ5_3: Q5.3 R105.1 R107.2 | length 283.5
  Bottom Layer w25: Q5.3@2735,1320.67 2735,1195 2771.5,1158.5 R107.2@2771.5,1145
  Bottom Layer w40: Q5.3@2735,1320.67 2769.33,1355 R105.1@2813.5,1355
NetQ7_1: Q7.1 R125.1 R129.2 | length 236.9
  Top Layer w20: 4380,1911.32 4380,1800 4407.4,1772.6 Q7.1@4427.24,1772.6
  Top Layer w30: R129.2@4336.5,1916.3 R125.1@4403.5,1916.3
NetQ8_1: Q8.1 R127.1 R130.2 | length 374.7
  Top Layer w25: Q8.1@3932.76,1947.4 3945.35,1960 4060,1960 4080,1940 4080,1865 4105.2,1839.8 R130.2@4132.91,1839.8
  Top Layer w40: R127.1@3852.52,1942.8 Q8.1@3928.15,1942.8
NetQ9_1: Q9.1 R141.2 U21.12 | length 798.5
  Top Layer w25: Q9.1@3747.4,2192.24 v1(3747.4,2240) R141.2@3747.4,2282.05 ; v1(4150,2370) 4152.91,2372.91 U21.12@4152.91,2429.37
  Bottom Layer w20: 3765,2240 3825,2300 3825,2435 3850,2460 4125,2460 4150,2435 v1(4150,2370)
  Bottom Layer w25: v1(3747.4,2240) 3765,2240
NetQ9_3: Q9.3 R128.1 | length 112.8
  Top Layer w40: Q9.3@3710,2097.76 R128.1@3822.76,2097.76
NetQ10_3: Q10.3 R129.1 | length 65
  Top Layer w25: R129.1@4275,1932.8 Q10.3@4275,1997.76
NetQ11_1: Q11.1 R139.2 R142.2 | length 178.9
  Top Layer w30: R142.2@4161.5,2135 4180.31,2116.18 ; R139.2@4177.91,2209.8 4180.31,2207.4 4180.31,2116.18 ; Q11.1@4180.31,2058.54 4180.31,2116.18
NetQ11_3: Q11.3 R130.1 | length 65.4
  Top Layer w25: R130.1@4132.91,1902.8 4142.91,1912.8 Q11.3@4142.91,1964.05
NetQ13_1: Q13.1 R149.1 R153.2 | length 487.3
  Top Layer w30: Q13.1@1043.5,1269.68 1043.5,1313.5 1070,1340 1150,1340 1166.69,1323.31 1166.69,1169.53 R149.1@1137.17,1140 R153.2@1204.17,1140 1179.17,1165 1174.65,1165
NetQ14_1: Q14.1 R152.1 R154.2 | length 284.6
  Top Layer w20: Q14.1@1270.32,1233.5 1270.32,1204.68 1290,1185 1351.5,1185 R154.2@1365,1171.5
  Top Layer w40: R154.2@1365,1171.5 1370.55,1177.05 R152.1@1510,1177.05
NetQ15_3: Q15.3 R153.1 | length 61.5
  Top Layer w30: Q15.3@1260,1081.5 1267.17,1088.66 R153.1@1267.17,1140
NetQ16_1: Q16.1 R164.2 R166.2 | length 185.9
  Top Layer w40: R164.2@1370,891.5 1370,1020 1400,1050 1415,1050
NetQ16_3: Q16.3 R154.1 | length 70.6
  Top Layer w40: R154.1@1365,1108.5 1366.5,1110 1435,1110
NetQ17_1: Q17.1 R167.2 U22.12 | length 731.9
  Top Layer w25: v1(1385,750) 1386.26,748.74 U22.12@1386.26,691.3
  Top Layer w40: v1@1772.6,952.6 1772.6,909.02 1778.5,903.11 R167.2@1778.5,855
  Bottom Layer w25: v1(1385,750) 1470,750 1490,730 1635,730 1645,740 1645,783.54 1689.19,827.73 1742.73,827.73 1775,860 v1(1775,955)
NetQ17_3: Q17.3 R155.1 | length 118.3
  Top Layer w40: R155.1@1690,1015 1798.5,1015 Q17.3@1805,1007.64
NetR22_2: R22.2 R23.1 | length 101.3
  Top Layer w60: R23.1@495.83,1330 R22.2@597.09,1330
NetR23_2: R23.2 R24.1 | length 95.8
  Top Layer w60: R24.1@285.83,1330 R23.2@381.65,1330
NetR24_2: R24.2 R25.1 | length 118.2
  Top Layer w60: R24.2@176.38,1334.72 R25.1@176.38,1452.91
NetR25_2: R25.2 R26.1 | length 112.4
  Top Layer w60: R25.2@179.29,1570 R26.1@291.65,1570
NetR26_2: R26.2 R27.1 | length 95.8
  Top Layer w60: R26.2@405.83,1570 R27.1@501.65,1570
NetR28_1: R28.1 R31.2 R35.2 | length 221.5
  Top Layer w50: R35.2@606.38,932.8 R31.2@606.38,1020 684,1020 700,1036 R28.1@700,1070
NetR29_2: R29.2 R30.1 | length 163.3
  Bottom Layer w25: R30.1@358.5,55 460,55 475,80 R29.2@475,112.64
NetR38_2: R38.2 R40.2 U9.3 | length 306.3
  Top Layer w15: R40.2@128.5,320 128.5,297.95 141.46,285 180,280 227.4,252.6 U9.3@284.61,252.6
  Top Layer w20: R38.2@300,180.47 300,240 305,245
  Top Layer w25: U9.3@284.61,252.6 292.2,245 305,245 v1(330,245)
NetR39_2: R39.2 U8.7 | length 95
  Top Layer w25: R39.2@591.38,221.65 U8.7@591.38,316.69
NetR42_2: R42.2 U8.6 | length 95
  Top Layer w25: R42.2@541.38,221.65 U8.6@541.38,316.69
NetR45_2: R45.2 R48.1 U12.1 U12.6 | length 237.8
  Top Layer w25: R45.2@2368.62,920 2377.4,928.78 2377.4,990.87 U12.1@2377.4,1099.13
  Top Layer w30: R48.1@2368.62,865 R45.2@2368.62,920
NetR46_2: R46.2 R50.1 U13.1 U13.6 | length 279.3
  Top Layer w25: U13.1@3155.87,2067.4 3220,2067.4 ; R50.1@3225,2236.38 3221.38,2232.76 R46.2@3221.38,2170 3220,2168.62 3220,2067.4 ; U13.6@3264.13,2067.4 3220,2067.4
NetR47_1: R47.1 R51.2 U12.3 | length 127.8
  Top Layer w25: R51.2@2240,1143.62 2256.38,1160 R47.1@2301.38,1160 ; U12.3@2302.6,1099.13 R47.1@2302.6,1158.78
NetR49_1: R49.1 R54.2 U13.3 | length 358.2
  Top Layer w25: U13.3@3155.87,1992.6 3155.87,1969.13 3180,1945 3385,1945 3398.62,1958.62 R49.1@3398.62,2035
NetR51_1: R51.1 R56.2 U12.4 | length 154.1
  Top Layer w25: R51.1@2240,1096.38 R56.2@2240,1033.62 2278.7,1033.62 2302.6,1009.72 U12.4@2302.6,990.87
NetR52_2: R52.2 R55.2 U10.11 | length 2452.2
  Top Layer w35: U10.11@3937.05,691.3 3937.05,752.05 v1(3940,755)
  Top Layer w40: v1(2087.5,995) 2107.95,995 v1(2120,982.95) ; R55.2@2024.19,1005.94 2102.38,1005.94 2108.5,1012.06 R52.2@2108.5,1040 2058.24,1040 R55.2@2024.19,1005.94
  Power w30: v1(2305,740) 2305,685 2325,665 3925,665 3940,680 v1(3940,755)
  Bottom Layer w40: v1(2087.5,995) 2107.95,995 v1(2120,982.95) 2305,797.95 v1(2305,740)
NetR54_1: R54.1 R57.2 U13.4 | length 388.2
  Top Layer w25: v1(3160,2115) R57.2@3160,2236.38 ; U13.4@3264.13,1992.6 v1(3301.46,1992.6) R54.1@3338.78,1992.6
  Bottom Layer w30: v1(3160,2115) 3282.4,1992.6 v1(3301.46,1992.6)
NetR63_1: R63.1 R65.1 R66.1 TP10.1 U14.6 | length 391
  Top Layer w20: 2945,2195 2980,2230 TP10.1@2980,2285
  Top Layer w30: U14.6@2562.18,2433.43 2562.18,2193.37 R63.1@2595,2160.55
NetR67_1: R67.1 R68.1 R70.1 TP12.1 U14.4 | length 565.9
  Top Layer w10: TP12.1@1965,1915 1980,1930 1980,1935 2090,2045 2090,2140 2085,2145
  Top Layer w30: R68.1@2440,2160.55 2462.18,2182.73 U14.4@2462.18,2433.43
NetR71_2: R71.2 U14.16 | length 181
  Top Layer w40: R71.2@2195,2908.5 2195,2844.96 2224.96,2815 2300,2815
NetR80_2: R80.2 TP17.1 U14.7 | length 629.6
  Top Layer w10: R80.2@2677.91,2290 R80.2@2677.91,2297.91 ; R80.2@2680,2290 2735,2345 2930,2345 2960,2375 2960,2415 TP17.1@3010,2465
  Top Layer w25: U14.7@2612.18,2433.43 2612.18,2312.82 2635,2290 R80.2@2677.91,2290
NetR89_1: R89.1 R91.1 R93.1 TP19.1 U15.6 | length 430.3
  Top Layer w10: TP19.1@2460,845 2480,895 2559.45,974.45 R91.1@2570,974.45
  Top Layer w30: U15.6@2908.31,691.3 R89.1@2908.31,944.88
NetR94_1: R94.1 R95.1 R98.1 TP21.1 U15.4 | length 648.6
  Top Layer w10: R94.1@3335,974.45 R94.1@3359.45,974.45 ; 3415,1030 3415,1105 3445,1135 3445,1235 3500,1290 TP21.1@3510,1290
  Top Layer w20: R94.1@3375,985 3415,1030
  Top Layer w30: U15.4@3008.31,691.3 R98.1@3008.31,950
NetR97_1: R97.1 R171.2 U16.3 | length 181.7
  Top Layer w20: U16.3@3631.73,1456.58 3631.73,1374.84 3638.98,1367.6 R97.1@3638.98,1336.58
  Top Layer w30: R171.2@3573.07,1456.58 U16.3@3631.73,1456.58
NetR99_2: R99.2 U15.16 | length 314.2
  Top Layer w35: U15.16@3165.87,315 3370,315 3410,275 R99.2@3410,221.5
NetR106_2: R106.2 TP22.1 U15.7 | length 411
  Top Layer w25: TP22.1@2670,705 2670,742.91 R106.2@2777.09,850 2827.09,850 2858.31,818.78 U15.7@2858.31,691.3
NetR108_1: R108.1 R109.1 U17.4 | length 154.3
  Top Layer w25: U17.4@5244.13,1477.6 5304.09,1477.6 R108.1@5310,1483.5 5316.5,1490 5355,1490 5371.5,1506.5 R109.1@5385,1500
NetR121_1: R121.1 R128.2 R131.2 U20.3 | length 360.2
  Top Layer w30: R121.1@3741.5,2385 3741.5,2378.5 3791.5,2328.5 R131.2@3825,2328.5 3805,2308.5 3805,2210 R128.2@3830,2185 3860,2215 3900,2215 ; 3801.5,2323.5 3805,2320
NetR124_1: R124.1 U21.15 | length 189.4
  Top Layer w30: U21.15@4302.91,2429.37 4302.91,2392.09 4382.24,2312.76 R124.1@4382.24,2272.8
NetR134_1: R134.1 U21.14 | length 148.4
  Top Layer w30: U21.14@4252.91,2429.37 4252.91,2356.88 4298.3,2311.5 R134.1@4310,2311.5
NetR146_1: R146.1 U22.15 | length 179.4
  Top Layer w25: R146.1@1155.67,828.5 1155.67,789.33 1195,750 1210,750 1236.26,723.74 U22.15@1236.26,691.3
NetR147_1: R147.1 R155.2 R161.2 U23.3 | length 272.5
  Top Layer w15: U23.3@1614.29,940.59 1684.41,940.59 R155.2@1690,935
  Top Layer w20: R161.2@1695,841.5 R161.2@1708.5,841.5 ; R161.2@1695,851.5 1708.5,851.5 R147.1@1763.5,790
  Top Layer w40: R161.2@1690,850 R155.2@1690,935
NetR157_1: R157.1 U22.14 | length 130.5
  Top Layer w25: R157.1@1230,798.5 1286.26,742.24 U22.14@1286.26,691.3
NetU10_12: U10.12 U11.3 | length 206.8
  Top Layer w10: U11.3@3828.82,800.63 3828.82,818.82 3840,830 3865,830 3887.05,807.95
  Top Layer w20: U10.12@3887.05,691.3 3887.05,807.95
NetU10_13: U10.13 U11.4 | length 114.1
  Top Layer w10: 3848.5,743.5 U11.4@3848.5,800.63
  Top Layer w20: U10.13@3837.05,691.3 3837.05,732.05 3848.5,743.5
NetU10_14: U10.14 U11.2 | length 118.5
  Top Layer w10: 3809.13,759.13 U11.2@3809.13,800.63
  Top Layer w20: U10.14@3787.05,691.3 3787.05,737.05 3809.13,759.13
NetU20_1: U20.1 U21.11 | length 539.2
  Top Layer w15: v1(3860,2280) 3863.11,2276.89 U20.1@3893.62,2276.89 U20.1@3903.62,2276.89
  Top Layer w25: v1(4102.91,2372.91) U21.11@4102.91,2429.37
  Bottom Layer w15: v1(3860,2280) 3860,2420 3875,2435 4080,2435 4102.91,2412.09 v1(4102.91,2372.91)
NetU22_11: U22.11 U23.1 | length 457.6
  Top Layer w15: U23.1@1614.29,889.41 U23.1@1626.46,889.41
  Top Layer w20: U22.11@1436.26,691.3 1436.26,736.26 1460,760 1545,760 1575,730 1625,730 1645,750 1645,875 1631.87,888.13 U23.1@1614.29,888.13
OC_L: MD1.7 R84.2 R100.2 R160.1 R165.1 | length 4083
  Top Layer w35: R100.2@3261.5,880 v1(3350,880) 3380,880 v1(3385,885)
  Top Layer w40: R160.1@1531.5,1408.54 1601.46,1408.54 1620,1390 ; R165.1@1620,1328.54 1620,1390 ; v1(1625,1415) 1620,1410 1620,1390
  Power w20: 3050,1607.8 3062.2,1607.8 3175,1495 3175,1395 3160,1380
  Power w30: v1(1625,1415) 1700,1340 1700,1175 1795,1080 2130.4,1080 2265.4,1215 2660,1215 2730,1285 2730,1315.67 2754.33,1340 2925,1340 2984,1281 ; 2985,1280 3080,1280 3160,1380 ; MD1.7@2994.72,1607.8 3050,1607.8
  Bottom Layer w25: MD1.7@3017.8,1607.8 MD1.7@2994.72,1607.8 2994.72,1669.72 3030,1705 3325,1705 3420,1610 R84.2@3420,1447.09 3447.91,1447.09 3500,1395 3500,1315 3450,1265 3420,1265 3410,1255 3410,1180 3365,1135 3365,895 v1(3350,880)
  Bottom Layer w35: v1(3350,880) v1@3380,880 ; v1@3382.5,882.5 v1(3385,885)
OC_U: MD1.12 R73.2 R74.2 R137.1 R140.1 | length 3400.5
  Top Layer w40: R140.1@3467.52,1976.3 3467.52,1922.48 v1(3475,1915) 3493.7,1896.3 R137.1@3556.02,1896.3
  Power w20: v1(2070,2315) 2150,2395 2541.1,2395 2576.1,2360 2576.1,1716.1 2515,1655 2515,1585 2400,1470 MD1.12@2333.31,1470
  Bottom Layer w20: MD1.12@2333.31,1470 2400,1470 2514.41,1584.41 2514.41,1649.41 2570,1705 2675,1705 ; R74.2@2700,1747.91 2700,1730 2675,1705 ; v1(3475,1915) 2840,1915 2835,1910 2635,1910 2618.74,1893.74 2618.74,1815 2675,1758.74 2675,1705
  Bottom Layer w40: v1(2070,2315) 2073.5,2311.5 R73.2@2073.5,2260
OI_Inj_OI_L: J2.1 R143.1 R159.1 S4.2 | length 5059.3
  Top Layer w25: R159.1@1450,108.5 1450,70 1470,50 1610,50 1625,65 1625,205 1632.68,212.68 S4.2@1710,212.68
  Top Layer w40: 1635,120 v1(1660,120) ; S4.2@1710,212.68 1742.68,212.68 1750,220 R143.1@1750,280
  Bottom Layer w15: v1@1655,120 v1(1660,120) 2040,120 2100,180 2100,197.79 2139.96,237.75 3732.23,237.75 3799.98,170 4277.25,170 4345,237.75 4641.49,237.75 4737.25,333.51 5363.51,333.51 5395,365 5395,675 5360,710 5265,710 5246.77,728.23 J2.1@5246.77,814.96
OI_Inj_OI_U: J3.5 R118.1 R136.1 S1.2 | length 4417
  Top Layer w30: v1(3765,2850) 3765,2871.54 ; R118.1@3855,2910 3855,3085 3885,3115 4045,3115 4067.91,3092.09 R136.1@4067.91,3052.8
  Top Layer w50: 3735,2905 3740,2910 R118.1@3855,2910
  Bottom Layer w20: J3.5@300,2380 440,2380 465,2405 465,2645 545,2725 920,2725 955.1,2760.1 955.1,2795.1 1002.55,2842.55 3722.55,2842.55 3730,2850 v1(3765,2850) v1@3762.55,2847.55
PWM_Low_Inj_L: J2.5 U22.5 | length 4551.3
  Top Layer w30: v1(1385,255) 1386.26,256.26 U22.5@1386.26,307.44
  Bottom Layer w15: v1(1385,255) 1385,265 1425,305 1425,305.1 4613.6,305.1 4709.35,400.86 5090,400.86 5109.25,420.1 5109.25,650.75 5144.9,686.4 5144.9,995 5164.86,1014.96 J2.5@5246.77,1014.96
PWM_Low_Inj_U: J3.8 U21.5 | length 4473.4
  Top Layer w25: v1(4150,2875) 4152.91,2872.09 U21.5@4152.91,2813.23
  Bottom Layer w15: J3.8@200,2280 250,2330 410,2330
  Bottom Layer w20: 410,2330 465,2330 492.55,2357.55 492.55,2631.37 553.63,2692.45 945,2692.45 982.55,2730 982.55,2776.37 1021.18,2815 4135,2815 4150,2830 v1(4150,2875)
PWM_out_L: J2.6 R113.2 U22.6 | length 4689.5
  Top Layer w30: U22.6@1436.26,307.44 1436.26,248.74 1455,230 1485,230 1520,195 R113.2@1520,171.5
  Top Layer w45: v1@1500,225 v1(1505,230)
  Bottom Layer w15: v1(1505,230) 1505,257.65 1530,282.65 4622.9,282.65 4718.65,378.4 5110.95,378.4 5132.55,400 5132.55,642.3 ; 5135,644.75 5132.55,642.3 ; J2.6@5346.77,1014.96 5296.81,965 5172.35,965 5167.35,960 5167.35,677.1 5132.55,642.3
PWM_out_U: J3.6 R111.2 U21.6 | length 4663.4
  Top Layer w25: R111.2@4000,2983.5 4000,2960 4025,2935 4070,2935 4102.91,2902.09 U21.6@4102.91,2813.23
  Top Layer w30: 4000,2960 v1(4000,2930) 4020,2930
  Bottom Layer w15: J3.6@200,2380 250.05,2430.05 250.05,2500.69 279.31,2529.95 349.95,2529.95
  Bottom Layer w20: 349.95,2529.95 364.95,2529.95 407.55,2572.55 407.55,2827.55 662.45,3082.45 2847.55,3082.45 2905,3025 2905,2975 2950,2930 v1(4000,2930)
RDY_L: C94.1 D29.1 J2.12 R85.1 U15.12 | length 4641.7
  Top Layer w25: C94.1@2873.44,143.62 R85.1@2924.75,143.62 2924.75,179.75 2958.31,213.31 U15.12@2958.31,307.44
  Top Layer w30: v1@2841.38,143.62 C94.1@2873.44,143.62
  Top Layer w35: v1@4871.65,78.35 D29.1@4913.5,78.35
  Power w20: v1(4870,80) 5180,80 5225,125 5225,210 5300,285 5445,285 5480,320 5480,1275 5440.04,1314.96 J2.12@5346.77,1314.96
  Ground w20: v1(2840,145) 2840,235 2940,335 4860,335 4935,260 4935,127.28 4887.72,80 v1(4870,80)
RDY_U: C83.1 D24.1 J3.12 R59.1 U14.12 | length 3881.6
  Top Layer w25: J3.12@200,2080 75,2080 55,2100 55,2795 125,2865 200,2865 335,3000 D24.1@478.5,3000 ; v1(2490,3020) 2530,3020 ; U14.12@2512.18,2817.28 2512.18,2894.2 ; 2523.62,2921.38 R59.1@2485,2921.38 2512.18,2894.2 ; C83.1@2560.55,3030 2540,3030 2530,3020 ; 2512.18,2894.2 2525,2907.02 2525,3015 2530,3020
  Top Layer w35: 410,3015 v1(410,3035)
  Power w25: v1(410,3035) 1585,3035 1632.45,3082.45 2457.55,3082.45 2490,3050 v1(2490,3020)
RSET_L: R18.2 R21.2 U6.7 | length 166.9
  Top Layer w15: U6.7@5114.93,1112.59 5138.89,1112.59 R18.2@5155.47,1129.17
  Top Layer w20: R18.2@5155.47,1129.17 R18.2@5165,1129.17
  Top Layer w30: R21.2@5155,1235 5155,1213.21 5165,1203.21 R18.2@5165,1129.17
RSET_U: R7.2 R11.2 U2.7 | length 161.9
  Top Layer w15: R7.2@457.1,2203.5 R7.2@463.5,2203.5 ; R7.2@457.1,2208.5 478.6,2230.01 U2.7@512.29,2230.01
  Top Layer w40: R11.2@457.1,2112.1 R7.2@457.1,2203.5
RST/EN_L: C96.1 D27.1 J2.10 R87.1 U15.14 | length 3774.4
  Top Layer w25: U15.14@3058.31,307.44 3058.31,221.69 3136.38,143.62 ; R87.1@3158.69,143.62 C96.1@3210,143.62
  Top Layer w35: v1@3121.38,143.62 3136.38,143.62 R87.1@3158.69,143.62 ; v1@4870,210 D27.1@4913.5,210
  Power w20: v1@4870,210 5146.76,210 5277.08,340.32 5415,340.32 5424.68,350 5424.68,1200 5409.72,1214.96 J2.10@5346.77,1214.96
  Ground w20: v1(3120,145) 3120,225 3175,280 4830,280 4870,240 v1@4870,210
  other v1: 4870,200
